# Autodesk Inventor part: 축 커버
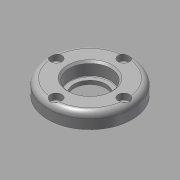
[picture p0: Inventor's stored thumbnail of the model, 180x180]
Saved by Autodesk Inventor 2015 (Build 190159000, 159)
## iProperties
Created: 2015-10
Part Number: 축 커버
Document SubType Name: Modeling
Designer: mdu
Density: 7.86 g/cm^3
Material: 강철, 연강
Mass: 76.1267 g
Surface Area: 48.0703 cm^2
Volume: 9.68533 cm^3
Appearance: 강철
Author: mdu
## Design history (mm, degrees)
sketch "스케치1"
  geometry: C1 r 22.355 at (0, 0) reference; C2 r 14 at (0, 0) reference; C3 r 1.23 at (0, 18) reference; 1 further point
extrude "돌출1" new body sketch "스케치1" distance "d0" = 8; taper "d1" = 0 deg
sketch "스케치2"
  geometry: C1 r 14 at (0, 0) reference; 1 further point
extrude "돌출2" join sketch "스케치2" distance "d2" = 3; taper "d3" = 0 deg
hole "구멍1" diameter "d6" = 17; stored, may be unused: countersink angle "d10" = 90 deg, drill point angle "d12" = 118 deg; dims "d4" = 10, "d5" = 10, "d7" = 6, "d8" = 23, "d9" = 2, "d11" = 8
hole "구멍2" diameter "d15" = 22; stored, may be unused: countersink angle "d19" = 90 deg, drill point angle "d21" = 0 deg; dims "d13" = 10, "d14" = 10, "d16" = 6, "d17" = 25, "d18" = 2, "d20" = 7
fillet "모깎기1" dims "d22" = 3, "d23" = 0.3
chamfer "모따기1" distance "d24" = 1; stored, may be unused: second distance "d25" = 2, angle "d26" = 45 deg
sketch "스케치3"
  geometry: 2 further points
hole "구멍3" sketch "스케치3" at (0, 18) diameter "d27" = 3.4; stored, may be unused: countersink angle "d31" = 90 deg, drill point angle "d33" = 118 deg; dims "d28" = 6, "d29" = 6, "d30" = 3.3, "d32" = 7
node "솔리드1"
pattern_circular "원형 패턴1" dims angle "d35" = 360 deg
node "참조1"
node "참조2"
node "참조3"
